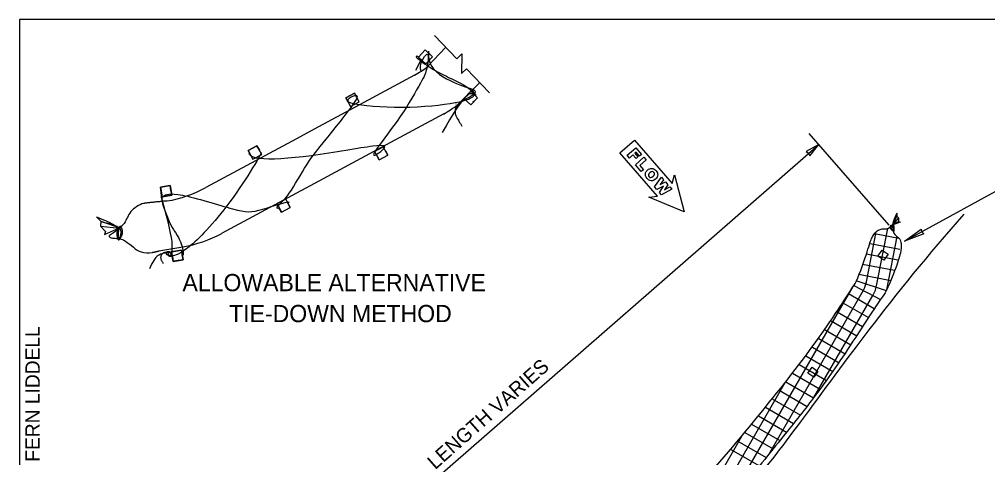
# Model space of a CAD drawing. Extents: x 99862 to 103680, y 99470 to 102076.
# Drawn here: x 99862 to 100941, y 101587 to 102076 of the extents above; entities that cross this region are included whole.
import ezdxf

# ---------------------------------------------------------------- set-up
doc = ezdxf.new("R2010")
doc.units = 0
for name, color, linetype in [('Level 1', 7, 'Continuous'), ('Level 10', 7, 'Continuous'), ('Level 15', 7, 'Continuous'), ('Level 20', 7, 'Continuous'), ('Level 3', 7, 'Continuous'), ('Level 4', 7, 'Continuous'), ('Level 6', 7, 'Continuous'), ('Level 62', 7, 'Continuous'), ('Level 8', 7, 'Continuous'), ('Level 9', 7, 'Continuous')]:
    doc.layers.add(name, color=color, linetype=linetype)

msp = doc.modelspace()

# ---------------------------------------------------------------- linework, layer by layer
at = {"layer": 'Level 1'}
msp.add_lwpolyline([(99862, 99999.5), (103151, 99999.5), (103151, 102075.5), (99862, 102075.5)], close=True, dxfattribs=at)
at = {"layer": 'Level 10'}
for p, q in [((100348.3, 101981.2), (100348.5, 101980.9)), ((100348.3, 101981.2), (100348.5, 101980.9)), ((100348.5, 101980.9), (100348.5, 101980.9)), ((100367.9, 101984.1), (100367.6, 101984.5)), ((100367.9, 101984.1), (100367.9, 101984.1))]:
    msp.add_line(p, q, dxfattribs=at)
at = {"layer": 'Level 15'}
for p, q in [((100831.6, 101846), (100742.4, 101948.2)), ((100027.7, 101303.7), (100752.9, 101936.2)), ((100848.6, 101828.3), (100994.7, 101908.4))]:
    msp.add_line(p, q, dxfattribs=at)
msp.add_lwpolyline([(100324.6, 102057.5), (100349.6, 102031.6), (100355.1, 102037), (100354.7, 102015.1), (100360.3, 102020.4), (100386.1, 101993.7)], dxfattribs=at)
for points in [[(100752.9, 101936.2), (100739.1, 101928.2), (100741.6, 101926.3), (100743.1, 101923.5)], [(100848.6, 101828.3), (100867.2, 101841.9), (100867.7, 101838.8), (100870.1, 101836.7)]]:
    msp.add_lwpolyline(points, close=True, dxfattribs=at)
at = {"layer": 'Level 20'}
for points in [[(100602.9, 101861.1), (100563.7, 101877.2), (100573.4, 101878.4), (100531.4, 101926.6), (100547.7, 101940.8), (100589.7, 101892.7), (100592.3, 101902.1), (100602.9, 101861.1)], [(100602.9, 101861.1), (100563.7, 101877.2), (100573.4, 101878.4), (100531.4, 101926.6), (100547.7, 101940.8), (100589.7, 101892.7), (100592.3, 101902.1), (100602.9, 101861.1)], [(100549, 101932.4), (100555.5, 101925), (100553.3, 101923), (100549.4, 101927.5), (100548.1, 101926.3), (100551.5, 101922.5), (100549.3, 101920.5), (100545.9, 101924.4), (100542, 101921), (100539.4, 101924), (100549, 101932.4)], [(100549, 101932.4), (100555.5, 101925), (100553.3, 101923), (100549.4, 101927.5), (100548.1, 101926.3), (100551.5, 101922.5), (100549.3, 101920.5), (100545.9, 101924.4), (100542, 101921), (100539.4, 101924), (100549, 101932.4)], [(100558.2, 101921.9), (100560.8, 101918.9), (100553.6, 101912.6), (100557.6, 101908), (100555.2, 101905.9), (100548.6, 101913.5), (100558.2, 101921.9)], [(100558.2, 101921.9), (100560.8, 101918.9), (100553.6, 101912.6), (100557.6, 101908), (100555.2, 101905.9), (100548.6, 101913.5), (100558.2, 101921.9)], [(100571.6, 101906.9), (100572.5, 101905.7), (100573.1, 101904.5), (100573.4, 101903.3), (100573.5, 101902.1), (100573.3, 101900.9), (100572.8, 101899.7), (100572, 101898.6), (100571, 101897.6), (100569.3, 101896.4), (100567.7, 101895.7), (100566.2, 101895.6), (100564.6, 101895.9), (100563.1, 101896.7), (100561.7, 101898.1), (100560.5, 101899.7), (100559.8, 101901.2), (100559.7, 101902.8), (100560, 101904.4), (100560.3, 101905.2), (100560.8, 101906), (100561.4, 101906.8), (100562.2, 101907.5), (100563.4, 101908.4), (100564.6, 101909), (100565.8, 101909.4), (100567, 101909.4), (100568.2, 101909.2), (100569.4, 101908.7), (100570.5, 101907.9), (100571.6, 101906.9)], [(100571.6, 101906.9), (100572.5, 101905.7), (100573.1, 101904.5), (100573.4, 101903.3), (100573.5, 101902.1), (100573.3, 101900.9), (100572.8, 101899.7), (100572, 101898.6), (100571, 101897.6), (100569.3, 101896.4), (100567.7, 101895.7), (100566.2, 101895.6), (100564.6, 101895.9), (100563.1, 101896.7), (100561.7, 101898.1), (100560.5, 101899.7), (100559.8, 101901.2), (100559.7, 101902.8), (100560, 101904.4), (100560.3, 101905.2), (100560.8, 101906), (100561.4, 101906.8), (100562.2, 101907.5), (100563.4, 101908.4), (100564.6, 101909), (100565.8, 101909.4), (100567, 101909.4), (100568.2, 101909.2), (100569.4, 101908.7), (100570.5, 101907.9), (100571.6, 101906.9)], [(100569.9, 101904), (100569.3, 101905), (100568.5, 101905.7), (100567.4, 101905.9), (100566.2, 101905.5), (100564.8, 101904.6), (100563.6, 101903.3), (100563.2, 101902.2), (100563.2, 101901.1), (100563.8, 101900.1), (100564.7, 101899.4), (100565.7, 101899.2), (100567, 101899.5), (100568.5, 101900.6), (100569.5, 101901.8), (100570, 101902.9), (100569.9, 101904)], [(100569.9, 101904), (100569.3, 101905), (100568.5, 101905.7), (100567.4, 101905.9), (100566.2, 101905.5), (100564.8, 101904.6), (100563.6, 101903.3), (100563.2, 101902.2), (100563.2, 101901.1), (100563.8, 101900.1), (100564.7, 101899.4), (100565.7, 101899.2), (100567, 101899.5), (100568.5, 101900.6), (100569.5, 101901.8), (100570, 101902.9), (100569.9, 101904)], [(100586.9, 101888.9), (100589.3, 101886.2), (100577.9, 101879.8), (100575.4, 101882.7), (100580, 101889.7), (100572.4, 101886.1), (100569.9, 101889), (100577.6, 101899.5), (100580.1, 101896.7), (100576.2, 101891.4), (100582.2, 101894.3), (100584.8, 101891.3), (100581.2, 101885.7), (100586.9, 101888.9)], [(100586.9, 101888.9), (100589.3, 101886.2), (100577.9, 101879.8), (100575.4, 101882.7), (100580, 101889.7), (100572.4, 101886.1), (100569.9, 101889), (100577.6, 101899.5), (100580.1, 101896.7), (100576.2, 101891.4), (100582.2, 101894.3), (100584.8, 101891.3), (100581.2, 101885.7), (100586.9, 101888.9)]]:
    msp.add_lwpolyline(points, dxfattribs=at)
at = {"layer": 'Level 3'}
for points in [[(100819, 101811.8), (100823.6, 101818.3), (100830.2, 101813.7), (100825.6, 101807.2)], [(100740.9, 101681.4), (100745.5, 101687.9), (100752, 101683.3), (100747.4, 101676.8)]]:
    msp.add_lwpolyline(points, close=True, dxfattribs=at)
at = {"layer": 'Level 4'}
for p, q in [((100806.2, 101782.9), (100817, 101838.9)), ((100815.1, 101837), (100842.4, 101831.7)), ((100817.9, 101780.3), (100830, 101842.6)), ((100810.2, 101825.7), (100843.2, 101819.3)), ((100828.9, 101774.2), (100840.4, 101833.4)), ((100806.1, 101814.3), (100841.1, 101807.5)), ((100801.8, 101802.9), (100837.4, 101796)), ((100795.5, 101784.2), (100828.3, 101773.2)), ((100797.7, 101791.4), (100833.4, 101784.5)), ((100650.6, 101534.1), (100791.4, 101777.9)), ((100697.2, 101590.8), (100802.7, 101773.6)), ((100792.2, 101779.1), (100821.7, 101763.3)), ((100747.6, 101654.1), (100813.3, 101767.9)), ((100786.2, 101769.9), (100814.9, 101753.3)), ((100773.4, 101749.6), (100801.9, 101733.1)), ((100779.8, 101759.7), (100808.3, 101743.3)), ((100766.8, 101739.6), (100795.5, 101723)), ((100760, 101729.6), (100788.9, 101712.9)), ((100753, 101719.8), (100782.3, 101702.9)), ((100745.9, 101710.1), (100775.6, 101692.9)), ((100738.7, 101700.4), (100768.8, 101683)), ((100731.3, 101690.8), (100761.8, 101673.2)), ((100723.9, 101681.2), (100754.6, 101663.5)), ((100617.1, 101500.1), (100715.7, 101670.9)), ((100716.3, 101671.7), (100747.3, 101653.8)), ((100701.2, 101652.7), (100732.5, 101634.6)), ((100708.8, 101662.2), (100740, 101644.2)), ((100693.6, 101643.3), (100724.9, 101625.2)), ((100685.9, 101633.8), (100717.2, 101615.7)), ((100678.2, 101624.4), (100709.6, 101606.3)), ((100583.9, 101466.5), (100667.4, 101611.2)), ((100670.5, 101615), (100702, 101596.8)), ((100662.8, 101605.6), (100694.4, 101587.4)), ((100655, 101596.3), (100686.8, 101577.9))]:
    msp.add_line(p, q, dxfattribs=at)
for centre, radius in [((100776.7, 101788.6), 30), ((100778.6, 101787.9), 40)]:
    msp.add_arc(centre, radius, 330, 349.042, dxfattribs=at)
at = {"layer": 'Level 6'}
for p, q in [((100314.4, 102041.5), (100306.9, 102033.4)), ((100322.5, 102033.9), (100314.4, 102041.5)), ((100306.9, 102033.4), (100314.9, 102025.9)), ((100314.9, 102025.9), (100322.5, 102033.9)), ((100316.3, 102036.4), (100316.3, 102036.4)), ((100225.8, 101988), (100235.5, 101993.2)), ((100235.5, 101993.2), (100225.8, 101988)), ((100225.8, 101988), (100225.8, 101988)), ((100228.4, 101983.1), (100225.8, 101988)), ((100225.8, 101988), (100225.8, 101988)), ((100225.8, 101988), (100231, 101978.3)), ((100235.5, 101993.2), (100235.5, 101993.2)), ((100235.5, 101993.2), (100238.1, 101988.3)), ((100235.5, 101993.2), (100235.5, 101993.2)), ((100240.7, 101983.5), (100235.5, 101993.2)), ((100231, 101978.3), (100240.7, 101983.5)), ((100231, 101978.3), (100231, 101978.3)), ((100240.7, 101983.5), (100240.7, 101983.5)), ((100117.1, 101929.5), (100126.8, 101934.7)), ((100126.8, 101934.7), (100117.1, 101929.5)), ((100126.8, 101934.7), (100126.8, 101934.7)), ((100126.8, 101934.7), (100126.8, 101934.7)), ((100126.8, 101934.7), (100129.5, 101929.9)), ((100132.1, 101925), (100126.8, 101934.7)), ((100126.9, 101934.7), (100126.9, 101934.7)), ((100257.9, 101928.4), (100267.6, 101933.6)), ((100117.1, 101929.5), (100117.1, 101929.5)), ((100117.1, 101929.5), (100117.1, 101929.5)), ((100119.7, 101924.6), (100117.1, 101929.5)), ((100117.1, 101929.5), (100122.4, 101919.7)), ((100117.2, 101929.4), (100117.2, 101929.4)), ((100122.4, 101919.7), (100132.1, 101925)), ((100132.1, 101925), (100132.1, 101925)), ((100263, 101919), (100260.4, 101923.8)), ((100263, 101919), (100272.7, 101924.2)), ((100270.1, 101929), (100272.7, 101924.2)), ((100122.4, 101919.7), (100122.4, 101919.7)), ((100019.2, 101888.5), (100030.1, 101890.4)), ((100019.2, 101888.5), (100030.1, 101890.4)), ((100030.1, 101890.4), (100019.2, 101888.5)), ((100030.1, 101890.4), (100030.1, 101890.4)), ((100030.1, 101890.4), (100030.1, 101890.4)), ((100030.1, 101890.4), (100031, 101884.9)), ((100030.1, 101890.4), (100032, 101879.5)), ((100032, 101879.5), (100030.1, 101890.4)), ((100030.1, 101890.3), (100030.1, 101890.3)), ((100019.2, 101888.5), (100019.2, 101888.5)), ((100019.2, 101888.5), (100019.2, 101888.5)), ((100020.1, 101883.1), (100019.2, 101888.5)), ((100019.2, 101888.5), (100019.2, 101888.5)), ((100021.1, 101877.6), (100019.2, 101888.5)), ((100019.2, 101888.5), (100021.1, 101877.6)), ((100032, 101879.5), (100021.1, 101877.6)), ((100021.1, 101877.6), (100032, 101879.5)), ((100032, 101879.5), (100032, 101879.5)), ((100021.1, 101877.6), (100021.1, 101877.6)), ((100161.4, 101870.6), (100164, 101865.7)), ((100154.3, 101860.5), (100151.7, 101865.3)), ((100031.7, 101816.3), (100042.6, 101818.2)), ((100042.6, 101818.2), (100031.7, 101816.3)), ((100031.7, 101816.3), (100033.6, 101805.9)), ((100033.6, 101805.8), (100032.6, 101811.3)), ((100044.4, 101807.7), (100033.6, 101805.9)), ((100033.6, 101805.9), (100044.4, 101807.7)), ((100043.5, 101813.2), (100044.4, 101807.7)), ((100044.4, 101807.7), (100044.4, 101807.7))]:
    msp.add_line(p, q, dxfattribs=at)
for points in [[(100225.8, 101988), (100228.4, 101983.1), (100228.4, 101983.1)], [(100225.8, 101988), (100225.8, 101988), (100225.8, 101988)], [(100238.1, 101988.3), (100238.1, 101988.3), (100235.5, 101993.2)], [(100235.5, 101993.2), (100235.5, 101993.2), (100235.5, 101993.2)], [(100365.1, 101995.4), (100372.8, 101988.2), (100372.8, 101988.2), (100365.2, 101980.1), (100365.2, 101980.1), (100357.5, 101987.4), (100365.1, 101995.4)], [(100129.5, 101929.9), (100129.5, 101929.9), (100126.8, 101934.7)], [(100257.9, 101928.4), (100263, 101919), (100263, 101919), (100272.7, 101924.2), (100272.7, 101924.2), (100267.6, 101933.6), (100257.9, 101928.4)], [(100272.7, 101924.2), (100272.7, 101924.2), (100267.6, 101933.6), (100267.6, 101933.6)], [(100117.1, 101929.5), (100119.7, 101924.6), (100119.7, 101924.6)], [(100257.9, 101928.4), (100257.9, 101928.4), (100263, 101919), (100263, 101919)], [(100260.4, 101923.8), (100263, 101919), (100263, 101919)], [(100272.7, 101924.2), (100272.7, 101924.2), (100270.1, 101929)], [(100031, 101884.9), (100031, 101884.9), (100030.1, 101890.4)], [(100019.2, 101888.5), (100020.1, 101883.1), (100020.1, 101883.1)], [(100149.3, 101869.9), (100154.3, 101860.5), (100154.3, 101860.5), (100164, 101865.7), (100164, 101865.7), (100159, 101875.1), (100149.3, 101869.9)], [(100164, 101865.7), (100164, 101865.7), (100161.4, 101870.6)], [(100151.7, 101865.3), (100154.3, 101860.5), (100154.3, 101860.5)], [(100031.7, 101816.3), (100033.6, 101805.9), (100033.6, 101805.8), (100044.4, 101807.7), (100044.4, 101807.7), (100042.6, 101818.2), (100031.7, 101816.3)], [(100033.6, 101805.8), (100033.6, 101805.8), (100031.7, 101816.3), (100031.7, 101816.3)], [(100031.7, 101816.3), (100031.7, 101816.3), (100033.6, 101805.8), (100033.6, 101805.8)], [(100042.6, 101818.2), (100042.6, 101818.2), (100044.4, 101807.7), (100044.4, 101807.7)], [(100044.4, 101807.7), (100044.4, 101807.7), (100042.6, 101818.2), (100042.6, 101818.2)], [(100032.6, 101811.3), (100033.6, 101805.8), (100033.6, 101805.8)], [(100044.4, 101807.7), (100044.4, 101807.7), (100043.5, 101813.2)]]:
    msp.add_lwpolyline(points, dxfattribs=at)
at = {"layer": 'Level 8'}
for points in [[(100337.2, 102044.5), (100316.8, 102022.8)], [(100302.4, 102013.3), (100241.1, 101980.3), (100190.7, 101953.2)], [(100350.2, 101980.1), (100375.1, 102005)], [(100214.7, 101905.6), (100266.4, 101933.4), (100335.3, 101970.5)], [(100190.7, 101953.2), (100170.8, 101942.5), (100069.9, 101888.1)], [(100087.6, 101837.1), (100196.1, 101895.5), (100214.7, 101905.6)], [(100017.6, 101817.4), (100044.2, 101822.1)]]:
    msp.add_lwpolyline(points, dxfattribs=at)
for centre, radius, start, end in [((100250, 102110.5), 110.4, 298.3103, 307.594), ((100282.6, 102067.4), 110.4, 298.1264, 307.7418), ((100002, 102014.1), 143.1, 279.8639, 298.3103), ((100019.7, 101963), 143.1, 279.8557, 298.3103)]:
    msp.add_arc(centre, radius, start, end, dxfattribs=at)
at = {"layer": 'Level 9'}
for p, q in [((99952.7, 101850.5), (99974, 101843.1)), ((100839.9, 101856.1), (100834.9, 101846.1)), ((100841.9, 101854.2), (100835, 101846.2)), ((99952.4, 101845), (99973.6, 101843)), ((100830, 101842.6), (100830, 101842.6))]:
    msp.add_line(p, q, dxfattribs=at)
for points in [[(100303.8, 102018.9), (100308.9, 102028.3), (100309, 102029.5), (100308.8, 102030.4), (100307.9, 102031.8), (100306.6, 102033.4), (100306, 102034), (100305, 102034.5), (100304.5, 102034.3), (100304.4, 102034.2), (100304.3, 102033.8), (100304.7, 102033), (100305.7, 102032), (100306.4, 102031.5), (100307.5, 102030.6), (100308.8, 102029.7), (100309.4, 102029.2), (100311.3, 102027.7), (100313.5, 102026.1), (100314.9, 102025.1), (100316.7, 102023.9), (100317.7, 102023.3), (100319.5, 102022.2), (100320.7, 102021.4), (100323.5, 102019.8), (100325, 102019), (100328.1, 102017.2), (100330.3, 102016.1), (100334.7, 102013.8), (100337.9, 102012.1), (100340.3, 102010.9), (100344.9, 102008.8), (100349.1, 102006.7), (100354.5, 102004), (100356.9, 102002.6), (100362.1, 101999.3), (100365, 101997.1), (100366.6, 101995.7), (100369.1, 101993.4), (100370, 101992.2), (100370.3, 101991.6), (100370.3, 101990.8), (100370, 101990.2), (100370, 101990.2)], [(100019.8, 101885.2), (100019.7, 101885.2), (100019.7, 101884.4), (100019.7, 101883.8), (100019.7, 101882.2), (100019.9, 101879.1), (100020.1, 101877.2), (100020.7, 101873.9), (100021.1, 101872), (100021.7, 101870), (100023.1, 101865.6), (100025, 101860.5), (100029.7, 101848.3)], [(100839.9, 101859.5), (100839.9, 101856.1), (100841.9, 101854.2), (100841.8, 101850.2), (100843.6, 101849.4), (100834.9, 101846.2)], [(99947.9, 101855.5), (99952.7, 101850.5), (99952.4, 101845), (99958.1, 101839.2), (99956.8, 101835.7), (99973.7, 101843.2)], [(100029.7, 101848.3), (100032.3, 101843.4), (100033.7, 101841.2), (100034.5, 101840), (100035.9, 101838), (100038, 101834.6), (100039.3, 101832.3), (100040.1, 101830.7), (100041.5, 101827.5), (100042.7, 101824.3), (100043.4, 101822.3), (100044.3, 101818.5), (100044.6, 101816.1), (100044.6, 101815), (100044.4, 101813.3), (100044.1, 101812.7), (100043.7, 101812.2)]]:
    msp.add_lwpolyline(points, dxfattribs=at)
for points, degree in [([(100310, 102017.9), (100306.3, 102023.6), (100320.4, 102047.4), (100316, 102018), (100312.6, 102010.4), (100287.6, 101966.7), (100256.1, 101926.9), (100256.7, 101923.6), (100259.7, 101924.3), (100270.2, 101932.2), (100270.2, 101937.7), (100184, 101921.6), (100119.3, 101917.6), (100117.4, 101925.9), (100118.7, 101927.2)], 3), ([(100318.1, 102039.9), (100316.8, 102022.8), (100338.7, 102006.9), (100368.2, 101997.6), (100370, 101996.5), (100369.9, 101994.4)], 3), ([(100151.8, 101865.2), (100149.5, 101864.3), (100147.4, 101866.3), (100161.7, 101877), (100183, 101916.6), (100200.1, 101937.1), (100240.4, 101987.2), (100239.1, 101992), (100227.5, 101987.3), (100225.9, 101980.5), (100299.1, 101975.7), (100361.4, 101983.8), (100370.3, 101991.6), (100369.5, 101992.8), (100357.3, 101992.8), (100333.3, 101949.4)], 3), ([(100369.9, 101994.4), (100370, 101992.2), (100356.4, 101985.2), (100350.2, 101980.1), (100348.5, 101977.5), (100347.2, 101971.7), (100349.4, 101966), (100355.3, 101956.4)], 2), ([(100131.3, 101927.6), (100132.1, 101925), (100090.8, 101858.8), (100043.5, 101813), (100027.5, 101810.6), (100036.4, 101819.9), (100020.1, 101877.2), (100021.1, 101877.6), (100032.7, 101885), (100110, 101860.2), (100125.5, 101860.2), (100167, 101875.4), (100161.5, 101870.4)], 3), ([(100000.5, 101870.4), (99995.7, 101869), (99983.8, 101861.7), (99980.9, 101847.9), (99964.5, 101835.4), (99961.8, 101835.4), (99961.8, 101832), (99969.3, 101831.6), (99974, 101831.1), (99979.4, 101829.5), (99989.6, 101821.2), (99996.6, 101815.4), (100006.3, 101815.3), (100010.3, 101815.8)], 3), ([(100026.6, 101873.1), (100010.2, 101871.7), (100000.5, 101870.4)], 2), ([(100914.8, 101858.4), (100834.8, 101768.5), (100713.9, 101597.8), (100624, 101489.7), (100391.3, 101318.5), (100354.2, 101297.7), (100106.5, 101188.7), (100064.3, 101178)], 3), ([(100839.9, 101859.5), (100833.8, 101846.4), (100836.7, 101843.5), (100837, 101838.2), (100832.8, 101842.4), (100833, 101844.5)], 2), ([(99947.9, 101855.5), (99973.8, 101845.1), (99969.9, 101837.8), (99972.3, 101827.3), (99978.1, 101837.9), (99976.5, 101841.7)], 2), ([(99976.5, 101841.7), (99975, 101845.8), (99972.6, 101843.3), (99971.5, 101829.4), (99975.7, 101834.6), (99975, 101845.2), (99955.1, 101849.3)], 2), ([(100831.7, 101843.7), (100833, 101844.5), (100833.5, 101845), (100835, 101846.4), (100836.4, 101846.2), (100836.8, 101844.6), (100836.5, 101840.2), (100836.3, 101838.4), (100837.2, 101835.9), (100842, 101832.2), (100843.7, 101830.3), (100844.7, 101826.3), (100845.1, 101825.8), (100844.9, 101816.4), (100839, 101798.5), (100829.4, 101774.1), (100825.4, 101768.4)], 3), ([(100833, 101844.5), (100833.1, 101846.6), (100834.6, 101845.7), (100837.1, 101839.3), (100834.4, 101841.2), (100833.2, 101846.3), (100841.8, 101850.2)], 2), ([(100793.5, 101781), (100797.2, 101788), (100807.6, 101817.7), (100811.6, 101832.8), (100817.2, 101839.5), (100821.6, 101841.7), (100825.6, 101842.4), (100828.5, 101841.8), (100830.2, 101842.7), (100829.7, 101842.4), (100831.7, 101843.7)], 3), ([(100031.9, 101815.5), (100028.5, 101816.7), (100027.1, 101816.5), (100025.5, 101815.7), (100025.4, 101814.1), (100027.4, 101812.9), (100029.3, 101812.1), (100031.6, 101813.4), (100030.1, 101815.8), (100027, 101815.8), (100013, 101812.3), (100007.1, 101797.6)], 2), ([(100010.3, 101815.8), (100014.4, 101816.7), (100018, 101817.5)], 2), ([(100032.5, 101811.6), (100030.2, 101811), (100028.7, 101811.2), (100027.7, 101816.5), (100020.7, 101814.9), (100018.7, 101808.5), (100022.4, 101803.6)], 2), ([(101202.5, 101785.8), (101114, 101672), (101039.8, 101564.6), (100900, 101393.5)], 3), ([(100227.6, 101276.5), (100237.1, 101281.1), (100255, 101288), (100379.6, 101356.9), (100534, 101468.5), (100619.3, 101553.3), (100695.7, 101645.2), (100759.1, 101726.3), (100788.3, 101773.3), (100793.5, 101781)], 3), ([(100825.4, 101768.4), (100816.1, 101755.8), (100779.2, 101697.1), (100742.2, 101646.4), (100709, 101605.6), (100650.9, 101532.8), (100614.1, 101497.5), (100553.3, 101435.2), (100395.4, 101324.3), (100286.6, 101263.4), (100254, 101251.3)], 3), ([(100773.6, 101323.7), (100781.4, 101330.9), (100796.5, 101342.8), (100895.3, 101445.3), (101010, 101597.3), (101066.6, 101703.4), (101091.8, 101763.7), (101093.9, 101768.8)], 3), ([(101130.9, 101764.4), (101125.8, 101751.6), (101102.9, 101693.1), (101078.1, 101648.6), (101038.3, 101571.1), (100920, 101418.7), (100833.9, 101328.5), (100806.3, 101307.4)], 3)]:
    msp.add_open_spline(points, degree=degree, dxfattribs=at)

# ---------------------------------------------------------------- texts
at = {"layer": 'Level 20'}
for s, p in [('ALLOWABLE ALTERNATIVE ', (100043.8, 101772.6)), ('TIE-DOWN METHOD', (100095.8, 101738.1))]:
    msp.add_text(s, height=19.2, dxfattribs=at).set_placement(p)
msp.add_text('LENGTH VARIES', height=16, rotation=41.5138, dxfattribs=at).set_placement((100325.5, 101573.1))
at = {"layer": 'Level 62'}
msp.add_text('DRAWN BY:  FERN LIDDELL', height=16, rotation=90, dxfattribs=at).set_placement((99884.7, 101449.4))

doc.saveas('drawing.dxf')
